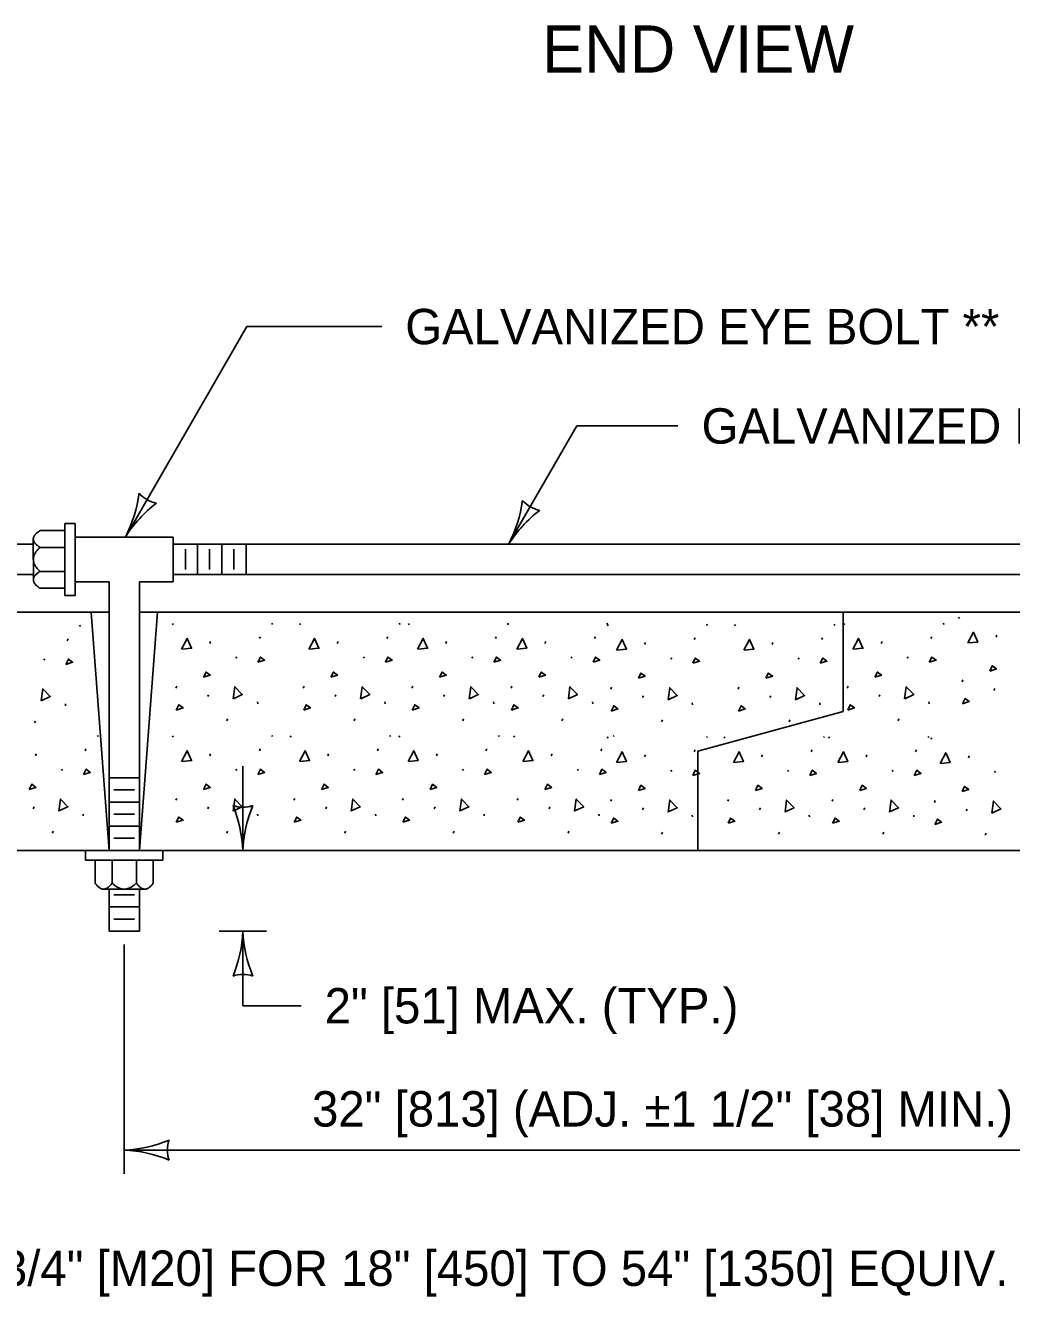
# Model space of a CAD drawing. Extents: x 49991.4 to 50021, y 49987.6 to 50011.4.
# Drawn here: x 50005.484 to 50007.156, y 50002.442 to 50004.599 of the extents above; entities that cross this region are included whole.
import ezdxf

# ---------------------------------------------------------------- set-up
doc = ezdxf.new("R2010")
doc.units = 0
for name, color, linetype in [('Level 1', 7, 'Continuous'), ('Level 2', 7, 'Continuous'), ('Level 3', 7, 'Continuous'), ('Level 5', 7, 'Continuous')]:
    doc.layers.add(name, color=color, linetype=linetype)

msp = doc.modelspace()

# ---------------------------------------------------------------- linework, layer by layer
at = {"layer": 'Level 1'}
for p, q in [((50005.5681, 50003.7537), (50005.5503, 50003.7537)), ((50005.5503, 50003.7537), (50005.5503, 50003.6318)), ((50005.5681, 50003.6928), (50005.5681, 50003.7537)), ((50005.497, 50003.7282), (50005.4973, 50003.6601)), ((50005.5503, 50003.7416), (50005.5086, 50003.7416)), ((50005.5681, 50003.7308), (50005.7345, 50003.7308)), ((50005.5681, 50003.6548), (50005.5681, 50003.7308)), ((50005.7345, 50003.6548), (50005.7345, 50003.7308)), ((50005.3982, 50003.7186), (50005.497, 50003.7186)), ((50005.5503, 50003.7132), (50005.5086, 50003.7132)), ((50005.7345, 50003.7186), (50007.8195, 50003.7186)), ((50005.755, 50003.6754), (50005.755, 50003.7103)), ((50005.7757, 50003.6672), (50005.7757, 50003.7186)), ((50005.7962, 50003.6754), (50005.7962, 50003.7103)), ((50005.8167, 50003.6672), (50005.8167, 50003.7186)), ((50005.8372, 50003.6754), (50005.8372, 50003.7103)), ((50005.8579, 50003.6672), (50005.8579, 50003.7186)), ((50005.5681, 50003.6318), (50005.5681, 50003.6928)), ((50005.3982, 50003.6672), (50005.4973, 50003.6672)), ((50005.5503, 50003.6725), (50005.5086, 50003.6725)), ((50005.7345, 50003.6672), (50007.7763, 50003.6672)), ((50005.5503, 50003.6439), (50005.5086, 50003.6439)), ((50005.5681, 50003.6548), (50005.6257, 50003.6548)), ((50005.6257, 50003.1988), (50005.6257, 50003.6548)), ((50005.677, 50003.6548), (50005.7345, 50003.6548)), ((50005.677, 50003.1988), (50005.677, 50003.6548)), ((50005.5503, 50003.6318), (50005.5681, 50003.6318)), ((50005.3226, 50003.603), (50005.6257, 50003.603)), ((50005.6257, 50003.1988), (50005.5951, 50003.6029)), ((50005.677, 50003.1988), (50005.7076, 50003.6031)), ((50005.677, 50003.603), (50007.8175, 50003.603)), ((50006.8706, 50003.4345), (50006.8706, 50003.603)), ((50005.5757, 50003.5812), (50005.5771, 50003.5791)), ((50005.7329, 50003.5839), (50005.7343, 50003.5818)), ((50005.9016, 50003.5847), (50005.903, 50003.5826)), ((50005.949, 50003.5839), (50005.9504, 50003.5818)), ((50006.1177, 50003.5847), (50006.1191, 50003.5826)), ((50006.1332, 50003.5839), (50006.1346, 50003.5818)), ((50006.3014, 50003.5839), (50006.3028, 50003.5818)), ((50006.3019, 50003.5847), (50006.3033, 50003.5826)), ((50006.4701, 50003.5847), (50006.4715, 50003.5826)), ((50006.4705, 50003.5822), (50006.4719, 50003.5801)), ((50006.6392, 50003.583), (50006.6406, 50003.5809)), ((50006.6866, 50003.5822), (50006.688, 50003.5801)), ((50006.8553, 50003.583), (50006.8567, 50003.5809)), ((50006.8717, 50003.5839), (50006.8731, 50003.5818)), ((50007.0404, 50003.5847), (50007.0418, 50003.5826)), ((50007.0665, 50003.5945), (50007.0679, 50003.5924)), ((50005.5547, 50003.5549), (50005.5562, 50003.5581)), ((50005.8806, 50003.5584), (50005.8821, 50003.5616)), ((50006.0967, 50003.5584), (50006.0982, 50003.5616)), ((50006.2809, 50003.5584), (50006.2824, 50003.5616)), ((50006.4491, 50003.5584), (50006.4506, 50003.5616)), ((50006.6182, 50003.5567), (50006.6197, 50003.5599)), ((50006.8343, 50003.5567), (50006.8358, 50003.5599)), ((50007.0194, 50003.5584), (50007.0209, 50003.5616)), ((50007.13, 50003.5608), (50007.1315, 50003.564)), ((50005.7964, 50003.5502), (50005.7979, 50003.5534)), ((50006.0125, 50003.5502), (50006.014, 50003.5534)), ((50006.1967, 50003.5502), (50006.1982, 50003.5534)), ((50006.3649, 50003.5502), (50006.3664, 50003.5534)), ((50006.534, 50003.5485), (50006.5355, 50003.5517)), ((50006.7501, 50003.5485), (50006.7516, 50003.5517)), ((50006.9352, 50003.5502), (50006.9367, 50003.5534)), ((50005.5149, 50003.524), (50005.5164, 50003.5218)), ((50005.8408, 50003.5275), (50005.8423, 50003.5253)), ((50006.0569, 50003.5275), (50006.0584, 50003.5253)), ((50006.2411, 50003.5275), (50006.2426, 50003.5253)), ((50006.4093, 50003.5275), (50006.4108, 50003.5253)), ((50006.5784, 50003.5258), (50006.5799, 50003.5236)), ((50006.7945, 50003.5258), (50006.796, 50003.5236)), ((50006.9796, 50003.5275), (50006.9811, 50003.5253)), ((50005.7389, 50003.4745), (50005.7403, 50003.4777)), ((50005.955, 50003.4745), (50005.9564, 50003.4777)), ((50006.1392, 50003.4745), (50006.1406, 50003.4777)), ((50006.3074, 50003.4745), (50006.3088, 50003.4777)), ((50006.4765, 50003.4728), (50006.4779, 50003.476)), ((50006.6926, 50003.4728), (50006.694, 50003.476)), ((50006.8777, 50003.4745), (50006.8791, 50003.4777)), ((50007.0725, 50003.4851), (50007.0739, 50003.4883)), ((50007.1265, 50003.4706), (50007.1279, 50003.4738)), ((50005.5514, 50003.4476), (50005.5518, 50003.4444)), ((50005.7929, 50003.46), (50005.7943, 50003.4632)), ((50005.8773, 50003.4511), (50005.8777, 50003.4479)), ((50006.009, 50003.46), (50006.0104, 50003.4632)), ((50006.0934, 50003.4511), (50006.0938, 50003.4479)), ((50006.1932, 50003.46), (50006.1946, 50003.4632)), ((50006.2776, 50003.4511), (50006.278, 50003.4479)), ((50006.3614, 50003.46), (50006.3628, 50003.4632)), ((50006.4458, 50003.4511), (50006.4462, 50003.4479)), ((50006.5305, 50003.4583), (50006.5319, 50003.4615)), ((50006.6149, 50003.4494), (50006.6153, 50003.4462)), ((50006.7466, 50003.4583), (50006.748, 50003.4615)), ((50006.831, 50003.4494), (50006.8314, 50003.4462)), ((50006.9317, 50003.46), (50006.9331, 50003.4632)), ((50007.0161, 50003.4511), (50007.0165, 50003.4479)), ((50006.624, 50003.3674), (50006.8706, 50003.4345)), ((50005.4993, 50003.4153), (50005.5007, 50003.4185)), ((50005.8252, 50003.4188), (50005.8266, 50003.422)), ((50006.0413, 50003.4188), (50006.0427, 50003.422)), ((50006.2255, 50003.4188), (50006.2269, 50003.422)), ((50006.3937, 50003.4188), (50006.3951, 50003.422)), ((50006.5628, 50003.4171), (50006.5642, 50003.4203)), ((50006.7789, 50003.4171), (50006.7803, 50003.4203)), ((50006.964, 50003.4188), (50006.9654, 50003.422)), ((50005.6058, 50003.3942), (50005.6072, 50003.3921)), ((50005.7329, 50003.3934), (50005.7343, 50003.3913)), ((50005.9016, 50003.3942), (50005.903, 50003.3921)), ((50005.933, 50003.3934), (50005.9344, 50003.3913)), ((50006.1017, 50003.3942), (50006.1031, 50003.3921)), ((50006.1172, 50003.3934), (50006.1186, 50003.3913)), ((50006.2859, 50003.3942), (50006.2873, 50003.3921)), ((50006.312, 50003.3934), (50006.3134, 50003.3913)), ((50006.4705, 50003.3917), (50006.4719, 50003.3896)), ((50006.4807, 50003.3942), (50006.4821, 50003.3921)), ((50006.6392, 50003.3925), (50006.6406, 50003.3904)), ((50006.6689, 50003.3917), (50006.6703, 50003.3896)), ((50006.8376, 50003.3925), (50006.839, 50003.3904)), ((50006.846, 50003.3917), (50006.8474, 50003.3896)), ((50007.0147, 50003.3925), (50007.0161, 50003.3904)), ((50007.0196, 50003.3899), (50007.021, 50003.3878)), ((50005.5006, 50003.3597), (50005.5021, 50003.3629)), ((50005.5848, 50003.3679), (50005.5863, 50003.3711)), ((50005.7964, 50003.3597), (50005.7979, 50003.3629)), ((50005.8806, 50003.3679), (50005.8821, 50003.3711)), ((50005.9965, 50003.3597), (50005.998, 50003.3629)), ((50006.0807, 50003.3679), (50006.0822, 50003.3711)), ((50006.1807, 50003.3597), (50006.1822, 50003.3629)), ((50006.2649, 50003.3679), (50006.2664, 50003.3711)), ((50006.3755, 50003.3597), (50006.377, 50003.3629)), ((50006.4597, 50003.3679), (50006.4612, 50003.3711)), ((50006.6182, 50003.3662), (50006.6197, 50003.3694)), ((50006.624, 50003.3674), (50006.624, 50003.1978)), ((50006.8166, 50003.3662), (50006.8181, 50003.3694)), ((50006.9937, 50003.3662), (50006.9952, 50003.3694)), ((50006.534, 50003.358), (50006.5355, 50003.3612)), ((50006.7324, 50003.358), (50006.7339, 50003.3612)), ((50006.9095, 50003.358), (50006.911, 50003.3612)), ((50007.0831, 50003.3562), (50007.0846, 50003.3594)), ((50005.545, 50003.337), (50005.5465, 50003.3348)), ((50005.677, 50003.3222), (50005.6257, 50003.3222)), ((50005.8408, 50003.337), (50005.8423, 50003.3348)), ((50006.0409, 50003.337), (50006.0424, 50003.3348)), ((50006.2251, 50003.337), (50006.2266, 50003.3348)), ((50006.4199, 50003.337), (50006.4214, 50003.3348)), ((50006.5784, 50003.3353), (50006.5799, 50003.3331)), ((50006.7768, 50003.3353), (50006.7783, 50003.3331)), ((50006.9539, 50003.3353), (50006.9554, 50003.3331)), ((50007.1275, 50003.3335), (50007.129, 50003.3313)), ((50005.6688, 50003.3017), (50005.6338, 50003.3017)), ((50005.677, 50003.281), (50005.6257, 50003.281)), ((50005.7389, 50003.284), (50005.7403, 50003.2872)), ((50005.939, 50003.284), (50005.9404, 50003.2872)), ((50006.1232, 50003.284), (50006.1246, 50003.2872)), ((50006.318, 50003.284), (50006.3194, 50003.2872)), ((50006.4765, 50003.2823), (50006.4779, 50003.2855)), ((50006.6749, 50003.2823), (50006.6763, 50003.2855)), ((50006.852, 50003.2823), (50006.8534, 50003.2855)), ((50007.0256, 50003.2805), (50007.027, 50003.2837)), ((50005.4971, 50003.2695), (50005.4985, 50003.2727)), ((50005.5815, 50003.2606), (50005.5819, 50003.2574)), ((50005.6688, 50003.2605), (50005.6338, 50003.2605)), ((50005.7929, 50003.2695), (50005.7943, 50003.2727)), ((50005.8773, 50003.2606), (50005.8777, 50003.2574)), ((50005.993, 50003.2695), (50005.9944, 50003.2727)), ((50006.0774, 50003.2606), (50006.0778, 50003.2574)), ((50006.1772, 50003.2695), (50006.1786, 50003.2727)), ((50006.2616, 50003.2606), (50006.262, 50003.2574)), ((50006.372, 50003.2695), (50006.3734, 50003.2727)), ((50006.4564, 50003.2606), (50006.4568, 50003.2574)), ((50006.5305, 50003.2678), (50006.5319, 50003.271)), ((50006.6149, 50003.2589), (50006.6153, 50003.2557)), ((50006.7289, 50003.2678), (50006.7303, 50003.271)), ((50006.8133, 50003.2589), (50006.8137, 50003.2557)), ((50006.906, 50003.2678), (50006.9074, 50003.271)), ((50006.9904, 50003.2589), (50006.9908, 50003.2557)), ((50007.0796, 50003.266), (50007.081, 50003.2692)), ((50005.677, 50003.24), (50005.6257, 50003.24)), ((50005.5294, 50003.2283), (50005.5308, 50003.2315)), ((50005.6688, 50003.2195), (50005.6338, 50003.2195)), ((50005.8252, 50003.2283), (50005.8266, 50003.2315)), ((50006.0253, 50003.2283), (50006.0267, 50003.2315)), ((50006.2095, 50003.2283), (50006.2109, 50003.2315)), ((50006.4043, 50003.2283), (50006.4057, 50003.2315)), ((50006.5628, 50003.2266), (50006.5642, 50003.2298)), ((50006.7612, 50003.2266), (50006.7626, 50003.2298)), ((50006.9383, 50003.2266), (50006.9397, 50003.2298)), ((50007.1119, 50003.2248), (50007.1133, 50003.228)), ((50008.1718, 50003.1988), (50005.3226, 50003.1988)), ((50005.6512, 50003.1988), (50005.487, 50003.1988)), ((50005.6512, 50003.1988), (50005.5855, 50003.1988)), ((50005.5855, 50003.1824), (50005.5855, 50003.1988)), ((50005.717, 50003.1988), (50005.6512, 50003.1988)), ((50005.717, 50003.1824), (50005.717, 50003.1988)), ((50005.5855, 50003.1824), (50005.717, 50003.1824)), ((50005.6019, 50003.1824), (50005.6019, 50003.1438)), ((50005.6307, 50003.1824), (50005.6307, 50003.1438)), ((50005.6719, 50003.1824), (50005.6719, 50003.1438)), ((50005.7006, 50003.1824), (50005.7006, 50003.1438)), ((50005.6156, 50003.1332), (50005.688, 50003.1333)), ((50005.6257, 50003.0619), (50005.6257, 50003.1332)), ((50005.677, 50003.0619), (50005.677, 50003.1333)), ((50005.6257, 50003.103), (50005.677, 50003.103)), ((50005.6338, 50003.1235), (50005.6688, 50003.1235)), ((50005.6338, 50003.0824), (50005.6688, 50003.0824)), ((50005.6257, 50003.0619), (50005.677, 50003.0619))]:
    msp.add_line(p, q, dxfattribs=at)
for points in [[(50005.7485, 50003.5406), (50005.7581, 50003.5587), (50005.7655, 50003.542), (50005.7488, 50003.5406)], [(50005.9646, 50003.5406), (50005.9742, 50003.5587), (50005.9816, 50003.542), (50005.965, 50003.5406)], [(50006.1488, 50003.5406), (50006.1584, 50003.5587), (50006.1658, 50003.542), (50006.1492, 50003.5406)], [(50006.317, 50003.5406), (50006.3266, 50003.5587), (50006.334, 50003.542), (50006.3174, 50003.5406)], [(50006.4861, 50003.5389), (50006.4957, 50003.557), (50006.5031, 50003.5403), (50006.4864, 50003.5389)], [(50006.7022, 50003.5389), (50006.7118, 50003.557), (50006.7192, 50003.5403), (50006.7026, 50003.5389)], [(50006.8873, 50003.5406), (50006.8969, 50003.5587), (50006.9043, 50003.542), (50006.8876, 50003.5406)], [(50007.0821, 50003.5512), (50007.0917, 50003.5693), (50007.0991, 50003.5526), (50007.0824, 50003.5512)], [(50005.5522, 50003.5147), (50005.5565, 50003.5236), (50005.5636, 50003.5183), (50005.5522, 50003.5147)], [(50005.8781, 50003.5182), (50005.8824, 50003.5271), (50005.8895, 50003.5218), (50005.8781, 50003.5182)], [(50006.0942, 50003.5182), (50006.0985, 50003.5271), (50006.1056, 50003.5218), (50006.0942, 50003.5182)], [(50006.2784, 50003.5182), (50006.2827, 50003.5271), (50006.2898, 50003.5218), (50006.2784, 50003.5182)], [(50006.4466, 50003.5182), (50006.4509, 50003.5271), (50006.458, 50003.5218), (50006.4466, 50003.5182)], [(50006.6157, 50003.5165), (50006.62, 50003.5254), (50006.6271, 50003.5201), (50006.6157, 50003.5165)], [(50006.8318, 50003.5165), (50006.8361, 50003.5254), (50006.8432, 50003.5201), (50006.8318, 50003.5165)], [(50007.0169, 50003.5182), (50007.0212, 50003.5271), (50007.0283, 50003.5218), (50007.0169, 50003.5182)], [(50007.1195, 50003.5034), (50007.1237, 50003.5123), (50007.1308, 50003.507), (50007.1195, 50003.5034)], [(50005.7859, 50003.4928), (50005.7901, 50003.5017), (50005.7972, 50003.4964), (50005.7859, 50003.4928)], [(50006.002, 50003.4928), (50006.0062, 50003.5017), (50006.0133, 50003.4964), (50006.002, 50003.4928)], [(50006.1862, 50003.4928), (50006.1904, 50003.5017), (50006.1975, 50003.4964), (50006.1862, 50003.4928)], [(50006.3544, 50003.4928), (50006.3586, 50003.5017), (50006.3657, 50003.4964), (50006.3544, 50003.4928)], [(50006.5235, 50003.4911), (50006.5277, 50003.5), (50006.5348, 50003.4947), (50006.5235, 50003.4911)], [(50006.7396, 50003.4911), (50006.7438, 50003.5), (50006.7509, 50003.4947), (50006.7396, 50003.4911)], [(50006.9247, 50003.4928), (50006.9289, 50003.5017), (50006.936, 50003.4964), (50006.9247, 50003.4928)], [(50005.5102, 50003.4528), (50005.513, 50003.4731), (50005.5257, 50003.46), (50005.5105, 50003.4529)], [(50005.8361, 50003.4563), (50005.8389, 50003.4766), (50005.8516, 50003.4635), (50005.8364, 50003.4564)], [(50006.0522, 50003.4563), (50006.055, 50003.4766), (50006.0677, 50003.4635), (50006.0525, 50003.4564)], [(50006.2364, 50003.4563), (50006.2392, 50003.4766), (50006.2519, 50003.4635), (50006.2367, 50003.4564)], [(50006.4046, 50003.4563), (50006.4074, 50003.4766), (50006.4201, 50003.4635), (50006.4049, 50003.4564)], [(50006.5737, 50003.4546), (50006.5765, 50003.4749), (50006.5892, 50003.4618), (50006.574, 50003.4547)], [(50006.7898, 50003.4546), (50006.7926, 50003.4749), (50006.8053, 50003.4618), (50006.7901, 50003.4547)], [(50006.9749, 50003.4563), (50006.9777, 50003.4766), (50006.9904, 50003.4635), (50006.9752, 50003.4564)], [(50007.0732, 50003.4478), (50007.0775, 50003.4567), (50007.0846, 50003.4514), (50007.0732, 50003.4478)], [(50005.7396, 50003.4372), (50005.7439, 50003.4461), (50005.751, 50003.4408), (50005.7396, 50003.4372)], [(50005.9557, 50003.4372), (50005.96, 50003.4461), (50005.9671, 50003.4408), (50005.9557, 50003.4372)], [(50006.1399, 50003.4372), (50006.1442, 50003.4461), (50006.1513, 50003.4408), (50006.1399, 50003.4372)], [(50006.3081, 50003.4372), (50006.3124, 50003.4461), (50006.3195, 50003.4408), (50006.3081, 50003.4372)], [(50006.4772, 50003.4355), (50006.4815, 50003.4444), (50006.4886, 50003.4391), (50006.4772, 50003.4355)], [(50006.6933, 50003.4355), (50006.6976, 50003.4444), (50006.7047, 50003.4391), (50006.6933, 50003.4355)], [(50006.8784, 50003.4372), (50006.8827, 50003.4461), (50006.8898, 50003.4408), (50006.8784, 50003.4372)], [(50005.7485, 50003.3501), (50005.7581, 50003.3682), (50005.7655, 50003.3515), (50005.7488, 50003.3501)], [(50005.9486, 50003.3501), (50005.9582, 50003.3682), (50005.9656, 50003.3515), (50005.949, 50003.3501)], [(50006.1328, 50003.3501), (50006.1424, 50003.3682), (50006.1498, 50003.3515), (50006.1332, 50003.3501)], [(50006.3276, 50003.3501), (50006.3372, 50003.3682), (50006.3446, 50003.3515), (50006.328, 50003.3501)], [(50006.4861, 50003.3484), (50006.4957, 50003.3665), (50006.5031, 50003.3498), (50006.4864, 50003.3484)], [(50006.6845, 50003.3484), (50006.6941, 50003.3665), (50006.7015, 50003.3498), (50006.6848, 50003.3484)], [(50006.8616, 50003.3484), (50006.8712, 50003.3665), (50006.8786, 50003.3498), (50006.862, 50003.3484)], [(50007.0352, 50003.3466), (50007.0448, 50003.3647), (50007.0522, 50003.348), (50007.0356, 50003.3466)], [(50005.5823, 50003.3277), (50005.5866, 50003.3366), (50005.5937, 50003.3313), (50005.5823, 50003.3277)], [(50005.8781, 50003.3277), (50005.8824, 50003.3366), (50005.8895, 50003.3313), (50005.8781, 50003.3277)], [(50006.0782, 50003.3277), (50006.0825, 50003.3366), (50006.0896, 50003.3313), (50006.0782, 50003.3277)], [(50006.2624, 50003.3277), (50006.2667, 50003.3366), (50006.2738, 50003.3313), (50006.2624, 50003.3277)], [(50006.4572, 50003.3277), (50006.4615, 50003.3366), (50006.4686, 50003.3313), (50006.4572, 50003.3277)], [(50006.6157, 50003.326), (50006.62, 50003.3349), (50006.6271, 50003.3296), (50006.6157, 50003.326)], [(50006.8141, 50003.326), (50006.8184, 50003.3349), (50006.8255, 50003.3296), (50006.8141, 50003.326)], [(50006.9912, 50003.326), (50006.9955, 50003.3349), (50007.0026, 50003.3296), (50006.9912, 50003.326)], [(50005.4901, 50003.3023), (50005.4943, 50003.3112), (50005.5014, 50003.3059), (50005.4901, 50003.3023)], [(50005.7859, 50003.3023), (50005.7901, 50003.3112), (50005.7972, 50003.3059), (50005.7859, 50003.3023)], [(50005.986, 50003.3023), (50005.9902, 50003.3112), (50005.9973, 50003.3059), (50005.986, 50003.3023)], [(50006.1702, 50003.3023), (50006.1744, 50003.3112), (50006.1815, 50003.3059), (50006.1702, 50003.3023)], [(50006.365, 50003.3023), (50006.3692, 50003.3112), (50006.3763, 50003.3059), (50006.365, 50003.3023)], [(50006.5235, 50003.3006), (50006.5277, 50003.3095), (50006.5348, 50003.3042), (50006.5235, 50003.3006)], [(50006.7219, 50003.3006), (50006.7261, 50003.3095), (50006.7332, 50003.3042), (50006.7219, 50003.3006)], [(50006.899, 50003.3006), (50006.9032, 50003.3095), (50006.9103, 50003.3042), (50006.899, 50003.3006)], [(50007.0726, 50003.2988), (50007.0768, 50003.3077), (50007.0839, 50003.3024), (50007.0726, 50003.2988)], [(50005.5403, 50003.2658), (50005.5431, 50003.2861), (50005.5558, 50003.273), (50005.5406, 50003.2659)], [(50005.8361, 50003.2658), (50005.8389, 50003.2861), (50005.8516, 50003.273), (50005.8364, 50003.2659)], [(50006.0362, 50003.2658), (50006.039, 50003.2861), (50006.0517, 50003.273), (50006.0365, 50003.2659)], [(50006.2204, 50003.2658), (50006.2232, 50003.2861), (50006.2359, 50003.273), (50006.2207, 50003.2659)], [(50006.4152, 50003.2658), (50006.418, 50003.2861), (50006.4307, 50003.273), (50006.4155, 50003.2659)], [(50006.5737, 50003.2641), (50006.5765, 50003.2844), (50006.5892, 50003.2713), (50006.574, 50003.2642)], [(50006.7721, 50003.2641), (50006.7749, 50003.2844), (50006.7876, 50003.2713), (50006.7724, 50003.2642)], [(50006.9492, 50003.2641), (50006.952, 50003.2844), (50006.9647, 50003.2713), (50006.9495, 50003.2642)], [(50007.1228, 50003.2623), (50007.1256, 50003.2826), (50007.1383, 50003.2695), (50007.1231, 50003.2624)], [(50005.7396, 50003.2467), (50005.7439, 50003.2556), (50005.751, 50003.2503), (50005.7396, 50003.2467)], [(50005.9397, 50003.2467), (50005.944, 50003.2556), (50005.9511, 50003.2503), (50005.9397, 50003.2467)], [(50006.1239, 50003.2467), (50006.1282, 50003.2556), (50006.1353, 50003.2503), (50006.1239, 50003.2467)], [(50006.3187, 50003.2467), (50006.323, 50003.2556), (50006.3301, 50003.2503), (50006.3187, 50003.2467)], [(50006.4772, 50003.245), (50006.4815, 50003.2539), (50006.4886, 50003.2486), (50006.4772, 50003.245)], [(50006.6756, 50003.245), (50006.6799, 50003.2539), (50006.687, 50003.2486), (50006.6756, 50003.245)], [(50006.8527, 50003.245), (50006.857, 50003.2539), (50006.8641, 50003.2486), (50006.8527, 50003.245)], [(50007.0263, 50003.2432), (50007.0306, 50003.2521), (50007.0377, 50003.2468), (50007.0263, 50003.2432)]]:
    msp.add_lwpolyline(points, dxfattribs=at)
for points in [[(50005.5086, 50003.7416), (50005.4856, 50003.7274), (50005.5086, 50003.7132)], [(50005.5086, 50003.7132), (50005.4856, 50003.6928), (50005.5086, 50003.6725)], [(50005.5086, 50003.6725), (50005.4856, 50003.6583), (50005.5086, 50003.6439)], [(50005.6019, 50003.1438), (50005.6163, 50003.1225), (50005.6307, 50003.1438)], [(50005.6307, 50003.1438), (50005.6512, 50003.1225), (50005.6719, 50003.1438)], [(50005.6719, 50003.1438), (50005.6862, 50003.1225), (50005.7006, 50003.1438)]]:
    msp.add_open_spline(points, degree=2, dxfattribs=at)
at = {"layer": 'Level 3'}
for p, q in [((50005.6532, 50003.7308), (50005.8594, 50004.0879)), ((50005.8594, 50004.0879), (50006.088, 50004.0879)), ((50006.3033, 50003.7186), (50006.4192, 50003.9192)), ((50006.4192, 50003.9192), (50006.5906, 50003.9192)), ((50005.8526, 50003.1988), (50005.8526, 50003.3418)), ((50005.8926, 50003.0619), (50005.8126, 50003.0619)), ((50005.8526, 50003.0619), (50005.8526, 50002.9354)), ((50005.8526, 50002.9354), (50005.9513, 50002.9354)), ((50005.6512, 50002.6904), (50007.843, 50002.6904))]:
    msp.add_line(p, q, dxfattribs=at)
for centre, radius, start, end in [((50005.446, 50003.8372), 0.233, 332.8248, 352.0746), ((50005.7173, 50003.8419), 0.0548, 222.1363, 257.8586), ((50006.0961, 50003.8251), 0.233, 332.8061, 352.0559), ((50006.3675, 50003.8296), 0.0548, 222.1176, 257.84), ((50005.841, 50003.6118), 0.2223, 127.4535, 147.637), ((50006.4911, 50003.5996), 0.2223, 127.4348, 147.6183), ((50005.8526, 50003.3272), 0.0548, 252.1388, 287.8612), ((50005.6199, 50003.1875), 0.233, 2.8273, 22.0772), ((50006.0748, 50003.1899), 0.2223, 157.456, 177.6395), ((50005.8526, 50003.327), 0.0548, 252.1388, 287.8612), ((50005.6199, 50003.1873), 0.233, 2.8273, 22.0772), ((50006.0748, 50003.1897), 0.2223, 157.456, 177.6395), ((50005.6305, 50003.0711), 0.2223, 337.456, 357.6395), ((50006.0853, 50003.0734), 0.233, 182.8273, 202.0772), ((50005.8526, 50002.9337), 0.0548, 72.1388, 107.8612), ((50005.6397, 50002.9231), 0.233, 272.8273, 292.0772), ((50005.7794, 50002.6904), 0.0548, 162.1388, 197.8612), ((50005.6421, 50002.4683), 0.2223, 67.456, 87.6395)]:
    msp.add_arc(centre, radius, start, end, dxfattribs=at)
at = {"layer": 'Level 5'}
msp.add_line((50005.6512, 50003.0396), (50005.6512, 50002.6504), dxfattribs=at)

# ---------------------------------------------------------------- texts
at = {"layer": 'Level 2'}
for s, height, p in [('END VIEW', 0.08, (50006.3601, 50004.5189)), ('GALVANIZED EYE BOLT **', 0.06, (50006.128, 50004.0579)), ('GALVANIZED BOLT **', 0.06, (50006.6306, 50003.8892)), ('2" [51] MAX. (TYP.)', 0.06, (50005.9913, 50002.9054)), ('32" [813] (ADJ. ±1 1/2" [38] MIN.)', 0.06, (50005.9699, 50002.7304)), ('3/4" [M20] FOR 18" [450] TO 54" [1350] EQUIV. SIZE 1" [M24] ', 0.06, (50005.4422, 50002.46))]:
    msp.add_text(s, height=height, dxfattribs=at).set_placement(p)

doc.saveas('drawing.dxf')
